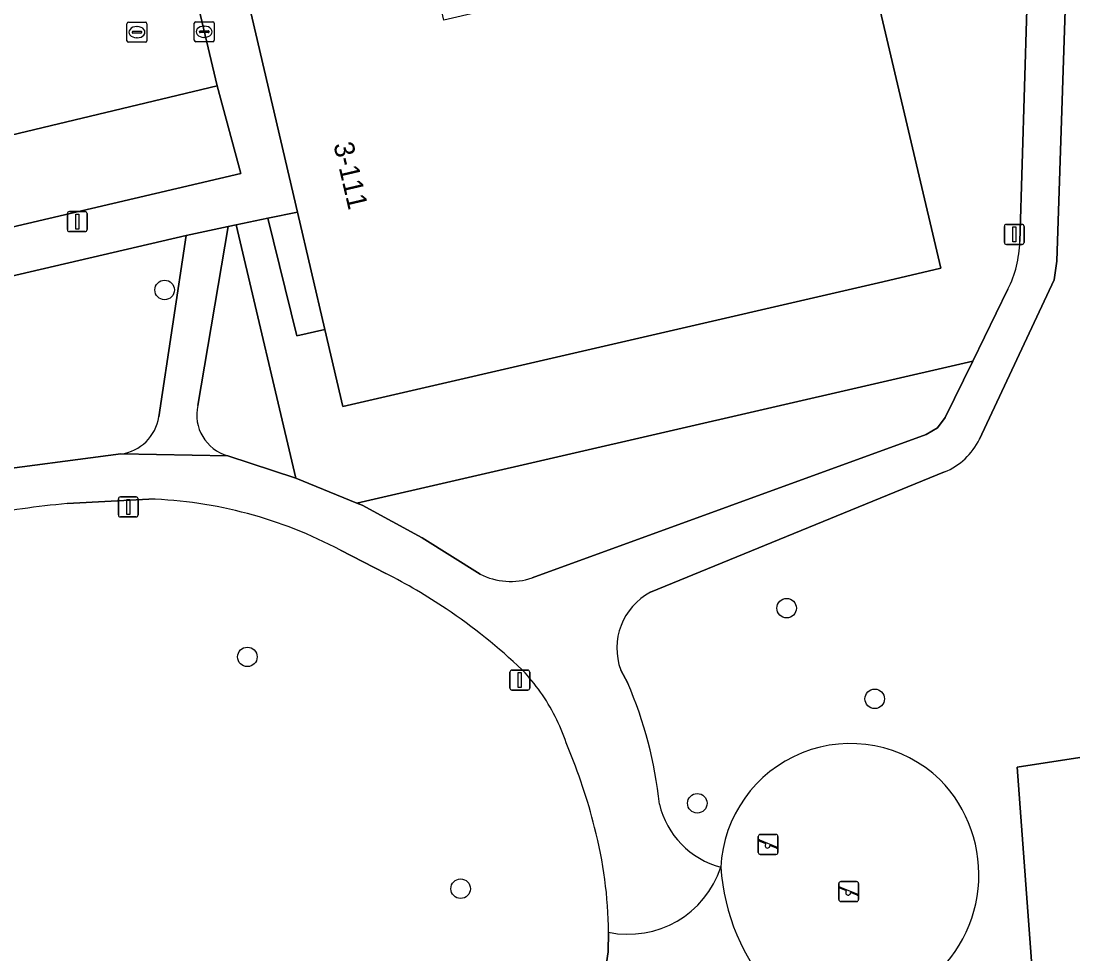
# Model space of a CAD drawing. Extents: x 162989 to 165008, y 383432 to 384338.
# Drawn here: x 164242.3 to 164294.9, y 383999.9 to 384046.6 of the extents above; entities that cross this region are included whole.
import ezdxf

# ---------------------------------------------------------------- set-up
doc = ezdxf.new("R2010")
doc.units = 0
for name, color, linetype in [('IMGEO_Boom', 7, 'Continuous'), ('IMGEO_Groenvoorziening', 7, 'Continuous'), ('IMGEO_Kolk', 7, 'Continuous'), ('IMGEO_Lichtmast', 7, 'Continuous'), ('IMGEO_Pand', 7, 'Continuous'), ('IMGEO_Pand_nummerreeks', 7, 'Continuous'), ('IMGEO_Parkeervlak_open', 7, 'Continuous'), ('IMGEO_Rijbaan_lokaal_open', 7, 'Continuous'), ('IMGEO_Rioolput', 7, 'Continuous'), ('IMGEO_Speelvoorziening', 7, 'Continuous'), ('IMGEO_Terreindeel_zand', 7, 'Continuous'), ('IMGEO_Voetpad_halfverhard', 7, 'Continuous'), ('IMGEO_Voetpad_open', 7, 'Continuous')]:
    doc.layers.add(name, color=color, linetype=linetype)

msp = doc.modelspace()

# ---------------------------------------------------------------- linework, layer by layer
at = {"layer": 'IMGEO_Boom'}
for centre in [(164249.448, 384033.16), (164280.603, 384017.221), (164253.594, 384014.78), (164285.014, 384012.681), (164276.127, 384007.448), (164264.273, 384003.167)]:
    msp.add_circle(centre, 0.489, dxfattribs=at)
at = {"layer": 'IMGEO_Groenvoorziening'}
for points in [[(164292.635, 384047.208), (164292.541, 384048.333), (164292.196, 384049.407), (164286.261, 384062.529), (164281.903, 384061.564), (164288.333, 384034.258), (164285.413, 384033.57), (164258.372, 384027.327), (164257.473, 384031.176), (164256.075, 384030.857), (164254.622, 384036.755), (164253.03, 384036.418), (164256.016, 384023.727), (164259.077, 384022.478), (164289.927, 384029.594), (164291.689, 384033.191)], [(164288.662, 383977.2), (164291.436, 383987.559), (164293.255, 383994.351), (164292.153, 384009.25), (164298.429, 384010.231), (164302.896, 384010.93), (164302.184, 384018.925), (164303.688, 384019.058), (164302.638, 384030.22), (164301.02, 384044.871), (164300.356, 384050.053), (164296.87, 384049.974)], [(164294.565, 384047.692), (164294.135, 384034.602), (164294.005, 384033.662), (164290.264, 384025.69)], [(164292.281, 384035.58), (164292.635, 384047.208)], [(164252.611, 384024.853), (164256.016, 384023.727), (164253.03, 384036.418), (164252.631, 384036.334), (164251.113, 384027.38)], [(164250.523, 384035.89), (164219.256, 384028.614)], [(164249.155, 384026.801), (164250.523, 384035.89)], [(164267.856, 384018.733), (164287.588, 384025.916), (164288.15, 384026.253), (164288.546, 384026.776), (164289.927, 384029.594), (164259.077, 384022.478), (164259.336, 384022.372), (164262.347, 384020.743), (164265.248, 384018.924)], [(164225.417, 384013.866), (164225.853, 384017.514), (164231.789, 384024.158), (164238.652, 384025.667), (164240.139, 384024.02), (164247.256, 384024.944)], [(164288.506, 384024.043), (164273.789, 384018.015)], [(164248.662, 384022.685), (164244.559, 384022.458)], [(164260.534, 384018.953), (164258.25, 384020.124)], [(164267.498, 384013.98), (164267.349, 384014.14)], [(164272.293, 384014.122), (164272.64, 384013.47)], [(164290.879, 383971.484), (164291.851, 383971.193), (164292.788, 383970.802), (164293.679, 383970.315), (164294.514, 383969.738), (164295.284, 383969.077), (164295.981, 383968.339), (164296.597, 383967.532), (164297.125, 383966.665), (164297.559, 383965.747), (164297.895, 383964.79), (164298.179, 383963.584), (164302.701, 383965.175), (164298.429, 384010.231), (164292.153, 384009.25), (164293.255, 383994.351), (164291.436, 383987.559)], [(164271.013, 383995.709), (164271.664, 384000), (164271.682, 384000.988)]]:
    msp.add_lwpolyline(points, dxfattribs=at)
for centre, radius, start, end in [((164286.473, 384035.751), 5.81, 333.8545, 358.3102), ((164253.187, 384026.902), 2.129, 167.0253, 254.2935), ((164246.972, 384027.133), 2.208, 277.3797, 351.339), ((164287.247, 384027.149), 3.351, 292.07, 334.1957), ((164248.547, 383978.561), 44.077, 95.1909, 101.0404), ((164247.985, 384000.923), 21.773, 61.8717, 88.2186), ((164247.779, 383993.698), 28.293, 56.1156, 63.2041), ((164266.783, 384021.988), 3.427, 243.3855, 288.2372), ((164275.259, 384015.216), 3.162, 117.7122, 200.2463), ((164246.823, 383992.448), 29.864, 46.5816, 55.9296), ((164260.237, 384007.364), 9.823, 34.1148, 42.3413), ((164253.699, 384005.254), 20.646, 5.9991, 23.4489), ((164260.132, 384007.271), 9.963, 17.7133, 34.2161), ((164244.197, 383999.509), 27.621, 14.0974, 23.0007), ((164283.794, 384003.946), 6.493, 46.2914, 177.3582), ((164283.431, 384003.87), 6.801, 303.4823, 44.5231), ((164278.385, 384008.368), 4.261, 192.9663, 255.3635), ((164250.156, 384000.804), 21.527, 0.4887, 14.6176)]:
    msp.add_arc(centre, radius, start, end, dxfattribs=at)
at = {"layer": 'IMGEO_Kolk'}
for p, q in [((164250.931, 384045.664), (164250.931, 384046.516)), ((164251.006, 384046.59), (164251.858, 384046.59)), ((164251.19, 384046.084), (164251.19, 384046.096)), ((164251.233, 384046.133), (164251.631, 384046.133)), ((164251.419, 384046.37), (164251.444, 384046.37)), ((164251.674, 384046.096), (164251.674, 384046.084)), ((164251.932, 384046.516), (164251.932, 384045.664)), ((164251.858, 384045.59), (164251.006, 384045.59)), ((164251.628, 384046.047), (164251.23, 384046.047)), ((164251.442, 384045.81), (164251.417, 384045.81))]:
    msp.add_line(p, q, dxfattribs=at)
for points in [[(164250.931, 384045.664), (164250.931, 384046.516)], [(164251.006, 384046.59), (164251.858, 384046.59)], [(164251.932, 384046.516), (164251.932, 384045.664)], [(164251.858, 384045.59), (164251.006, 384045.59)]]:
    msp.add_lwpolyline(points, dxfattribs=at)
for centre, radius, start, end in [((164251.008, 384046.514), 0.0765, 91.552, 178.448), ((164251.008, 384046.514), 0.0765, 91.552, 178.448), ((164251.23, 384046.093), 0.0403, 85.8775, 175.7526), ((164251.635, 384046.095), 0.0386, 1.7309, 96.639), ((164251.856, 384046.514), 0.0765, 1.552, 88.448), ((164251.856, 384046.514), 0.0765, 1.552, 88.448), ((164251.008, 384045.666), 0.0765, 181.552, 268.448), ((164251.008, 384045.666), 0.0765, 181.552, 268.448), ((164251.227, 384046.083), 0.0366, 178.938, 274.7102), ((164251.631, 384046.09), 0.043, 264.8664, 352.4533), ((164251.856, 384045.666), 0.0765, 271.552, 358.448), ((164251.856, 384045.666), 0.0765, 271.552, 358.448)]:
    msp.add_arc(centre, radius, start, end, dxfattribs=at)
for centre, major_axis, ratio, start_param, end_param in [((164251.418, 384046.09), (-0.387, 0.002), 0.722429, 4.712389, 7.853982), ((164251.443, 384046.09), (-0.39, 0.002), 0.717154, 1.570796, 4.712389)]:
    msp.add_ellipse(centre, major_axis=major_axis, ratio=ratio, start_param=start_param, end_param=end_param, dxfattribs=at)
at = {"layer": 'IMGEO_Lichtmast'}
for p, q in [((164244.576, 384036.182), (164244.576, 384036.982)), ((164244.576, 384036.982), (164244.576, 384036.182)), ((164244.676, 384037.082), (164245.466, 384037.082)), ((164245.466, 384037.082), (164244.676, 384037.082)), ((164245.566, 384036.982), (164245.566, 384036.182)), ((164245.566, 384036.182), (164245.566, 384036.982)), ((164245.466, 384036.082), (164244.676, 384036.082)), ((164244.676, 384036.082), (164245.466, 384036.082)), ((164291.508, 384035.543), (164291.508, 384036.343)), ((164291.508, 384036.343), (164291.508, 384035.543)), ((164291.608, 384036.443), (164292.398, 384036.443)), ((164292.398, 384036.443), (164291.608, 384036.443)), ((164292.498, 384036.343), (164292.498, 384035.543)), ((164292.498, 384035.543), (164292.498, 384036.343)), ((164292.398, 384035.443), (164291.608, 384035.443)), ((164291.608, 384035.443), (164292.398, 384035.443)), ((164247.13, 384021.889), (164247.13, 384022.689)), ((164247.13, 384022.689), (164247.13, 384021.889)), ((164247.23, 384022.789), (164248.02, 384022.789)), ((164248.02, 384022.789), (164247.23, 384022.789)), ((164248.12, 384022.689), (164248.12, 384021.889)), ((164248.12, 384021.889), (164248.12, 384022.689)), ((164248.02, 384021.789), (164247.23, 384021.789)), ((164247.23, 384021.789), (164248.02, 384021.789)), ((164266.743, 384013.218), (164266.743, 384014.018)), ((164266.743, 384014.018), (164266.743, 384013.218)), ((164266.843, 384014.118), (164267.633, 384014.118)), ((164267.633, 384014.118), (164266.843, 384014.118)), ((164267.733, 384014.018), (164267.733, 384013.218)), ((164267.733, 384013.218), (164267.733, 384014.018)), ((164267.633, 384013.118), (164266.843, 384013.118)), ((164266.843, 384013.118), (164267.633, 384013.118))]:
    msp.add_line(p, q, dxfattribs=at)
for points in [[(164244.996, 384036.957), (164245.146, 384036.957), (164245.146, 384036.207), (164244.996, 384036.207), (164244.996, 384036.957)], [(164291.928, 384036.318), (164292.078, 384036.318), (164292.078, 384035.568), (164291.928, 384035.568), (164291.928, 384036.318)], [(164247.55, 384022.664), (164247.7, 384022.664), (164247.7, 384021.914), (164247.55, 384021.914), (164247.55, 384022.664)], [(164267.163, 384013.993), (164267.313, 384013.993), (164267.313, 384013.243), (164267.163, 384013.243), (164267.163, 384013.993)]]:
    msp.add_lwpolyline(points, dxfattribs=at)
for centre, start, end in [((164244.676, 384036.982), 90, 180), ((164244.676, 384036.982), 90, 180), ((164245.466, 384036.982), 0, 90), ((164245.466, 384036.982), 360, 90), ((164244.676, 384036.182), 180, 270), ((164244.676, 384036.182), 180, 270), ((164245.466, 384036.182), 270, 0), ((164245.466, 384036.182), 270, 0), ((164291.608, 384036.343), 90, 180), ((164291.608, 384036.343), 90, 180), ((164292.398, 384036.343), 0, 90), ((164292.398, 384036.343), 360, 90), ((164291.608, 384035.543), 180, 270), ((164291.608, 384035.543), 180, 270), ((164292.398, 384035.543), 270, 0), ((164292.398, 384035.543), 270, 0), ((164247.23, 384022.689), 90, 180), ((164247.23, 384022.689), 90, 180), ((164248.02, 384022.689), 0, 90), ((164248.02, 384022.689), 360, 90), ((164247.23, 384021.889), 180, 270), ((164247.23, 384021.889), 180, 270), ((164248.02, 384021.889), 270, 0), ((164248.02, 384021.889), 270, 0), ((164266.843, 384014.018), 90, 180), ((164266.843, 384014.018), 90, 180), ((164267.633, 384014.018), 0, 90), ((164267.633, 384014.018), 360, 90), ((164266.843, 384013.218), 180, 270), ((164266.843, 384013.218), 180, 270), ((164267.633, 384013.218), 270, 0), ((164267.633, 384013.218), 270, 0)]:
    msp.add_arc(centre, 0.1, start, end, dxfattribs=at)
at = {"layer": 'IMGEO_Pand'}
msp.add_lwpolyline([(164281.903, 384061.564), (164272.695, 384059.396), (164274.092, 384054.262), (164274.51, 384052.47), (164274.837, 384051.068), (164270.485, 384050.053), (164270.869, 384048.402), (164263.436, 384046.666), (164262.745, 384049.627), (164262.679, 384049.912), (164254.084, 384047.905), (164253.594, 384047.791), (164256.099, 384037.062), (164257.473, 384031.176), (164258.372, 384027.327), (164285.413, 384033.57), (164288.333, 384034.258)], close=True, dxfattribs=at)
at = {"layer": 'IMGEO_Parkeervlak_open'}
msp.add_lwpolyline([(164216.414, 384032.688), (164216.912, 384030.477), (164253.269, 384038.999), (164252.072, 384043.378), (164228.984, 384037.862), (164226.367, 384037.236), (164213.994, 384034.28)], dxfattribs=at)
at = {"layer": 'IMGEO_Rijbaan_lokaal_open'}
msp.add_lwpolyline([(164236.086, 384046.718), (164227.391, 384044.691), (164228.984, 384037.862), (164252.072, 384043.378), (164249.058, 384056.151), (164247.449, 384062.968), (164245.302, 384072.068), (164243.675, 384078.963), (164235.037, 384115.701)], dxfattribs=at)
at = {"layer": 'IMGEO_Rioolput'}
for p, q in [((164247.561, 384045.644), (164247.561, 384046.496)), ((164247.636, 384046.57), (164248.488, 384046.57)), ((164247.863, 384046.113), (164248.261, 384046.113)), ((164248.049, 384046.35), (164248.074, 384046.35)), ((164248.562, 384046.496), (164248.562, 384045.644)), ((164248.488, 384045.57), (164247.636, 384045.57)), ((164247.82, 384046.064), (164247.82, 384046.076)), ((164248.258, 384046.027), (164247.86, 384046.027)), ((164248.072, 384045.79), (164248.047, 384045.79)), ((164248.304, 384046.076), (164248.304, 384046.064))]:
    msp.add_line(p, q, dxfattribs=at)
for points in [[(164247.561, 384045.644), (164247.561, 384046.496)], [(164247.636, 384046.57), (164248.488, 384046.57)], [(164248.562, 384046.496), (164248.562, 384045.644)], [(164248.488, 384045.57), (164247.636, 384045.57)]]:
    msp.add_lwpolyline(points, dxfattribs=at)
for centre, radius, start, end in [((164247.638, 384046.494), 0.0765, 91.552, 178.448), ((164247.638, 384046.494), 0.0765, 91.552, 178.448), ((164247.86, 384046.073), 0.0403, 85.8775, 175.7526), ((164248.265, 384046.075), 0.0386, 1.7309, 96.639), ((164248.486, 384046.494), 0.0765, 1.552, 88.448), ((164248.486, 384046.494), 0.0765, 1.552, 88.448), ((164247.638, 384045.646), 0.0765, 181.552, 268.448), ((164247.638, 384045.646), 0.0765, 181.552, 268.448), ((164247.857, 384046.063), 0.0366, 178.938, 274.7102), ((164248.261, 384046.07), 0.043, 264.8664, 352.4533), ((164248.486, 384045.646), 0.0765, 271.552, 358.448), ((164248.486, 384045.646), 0.0765, 271.552, 358.448)]:
    msp.add_arc(centre, radius, start, end, dxfattribs=at)
for centre, major_axis, ratio, start_param, end_param in [((164248.048, 384046.07), (-0.387, 0.002), 0.722429, 4.712389, 7.853982), ((164248.073, 384046.07), (-0.39, 0.002), 0.717154, 1.570796, 4.712389)]:
    msp.add_ellipse(centre, major_axis=major_axis, ratio=ratio, start_param=start_param, end_param=end_param, dxfattribs=at)
at = {"layer": 'IMGEO_Speelvoorziening'}
for p, q in [((164279.178, 384004.985), (164279.178, 384005.785)), ((164279.178, 384005.785), (164279.178, 384004.985)), ((164279.561, 384005.413), (164279.222, 384005.55)), ((164279.247, 384005.61), (164280.123, 384005.257)), ((164279.278, 384005.885), (164280.068, 384005.885)), ((164280.068, 384005.885), (164279.278, 384005.885)), ((164280.168, 384005.785), (164280.168, 384004.985)), ((164280.168, 384004.985), (164280.168, 384005.785)), ((164280.099, 384005.197), (164279.759, 384005.334)), ((164280.068, 384004.885), (164279.278, 384004.885)), ((164279.278, 384004.885), (164280.068, 384004.885)), ((164283.215, 384002.629), (164283.215, 384003.429)), ((164283.215, 384003.429), (164283.215, 384002.629)), ((164283.315, 384003.529), (164284.105, 384003.529)), ((164284.105, 384003.529), (164283.315, 384003.529)), ((164284.205, 384003.429), (164284.205, 384002.629)), ((164284.205, 384002.629), (164284.205, 384003.429)), ((164283.598, 384003.057), (164283.259, 384003.194)), ((164283.284, 384003.254), (164284.16, 384002.901)), ((164284.136, 384002.841), (164283.796, 384002.978)), ((164284.105, 384002.529), (164283.315, 384002.529)), ((164283.315, 384002.529), (164284.105, 384002.529))]:
    msp.add_line(p, q, dxfattribs=at)
for centre, radius, start, end in [((164279.278, 384005.785), 0.1, 90, 180), ((164279.278, 384005.785), 0.1, 90, 180), ((164279.235, 384005.58), 0.0327, 68.078, 248.078), ((164280.068, 384005.785), 0.1, 0, 90), ((164280.068, 384005.785), 0.1, 360, 90), ((164279.64, 384005.323), 0.12, 130.9928, 5.1632), ((164280.111, 384005.227), 0.0327, 248.078, 68.078), ((164279.278, 384004.985), 0.1, 180, 270), ((164279.278, 384004.985), 0.1, 180, 270), ((164280.068, 384004.985), 0.1, 270, 0), ((164280.068, 384004.985), 0.1, 270, 0), ((164283.315, 384003.429), 0.1, 90, 180), ((164283.315, 384003.429), 0.1, 90, 180), ((164284.105, 384003.429), 0.1, 0, 90), ((164284.105, 384003.429), 0.1, 360, 90), ((164283.272, 384003.224), 0.0327, 68.078, 248.078), ((164283.677, 384002.967), 0.12, 130.9928, 5.1632), ((164284.148, 384002.871), 0.0327, 248.078, 68.078), ((164283.315, 384002.629), 0.1, 180, 270), ((164283.315, 384002.629), 0.1, 180, 270), ((164284.105, 384002.629), 0.1, 270, 0), ((164284.105, 384002.629), 0.1, 270, 0)]:
    msp.add_arc(centre, radius, start, end, dxfattribs=at)
at = {"layer": 'IMGEO_Terreindeel_zand'}
for centre, radius, start, end in [((164283.794, 384003.946), 6.493, 46.2914, 177.3582), ((164283.431, 384003.87), 6.801, 303.4823, 44.5231), ((164287.842, 384004.937), 10.556, 183.7578, 221.7258)]:
    msp.add_arc(centre, radius, start, end, dxfattribs=at)
at = {"layer": 'IMGEO_Voetpad_halfverhard'}
for points in [[(164291.955, 384054.83), (164288.224, 384062.997), (164286.261, 384062.529), (164292.196, 384049.407), (164292.541, 384048.333), (164292.635, 384047.208), (164292.281, 384035.58)], [(164290.264, 384025.69), (164294.005, 384033.662), (164294.135, 384034.602), (164294.565, 384047.692), (164293.767, 384052.02), (164292.649, 384053.999)], [(164252.631, 384036.334), (164250.523, 384035.89), (164249.155, 384026.801)], [(164251.113, 384027.38), (164252.631, 384036.334)], [(164291.689, 384033.191), (164289.927, 384029.594), (164288.546, 384026.776), (164288.15, 384026.253), (164287.588, 384025.916), (164267.856, 384018.733)], [(164265.248, 384018.924), (164262.347, 384020.743), (164259.336, 384022.372), (164259.077, 384022.478), (164256.016, 384023.727), (164252.611, 384024.853), (164247.256, 384024.944), (164240.139, 384024.02), (164232.148, 384022.19), (164225.417, 384013.866)], [(164247.256, 384024.944), (164252.611, 384024.853)], [(164273.789, 384018.015), (164288.506, 384024.043)], [(164244.559, 384022.458), (164248.662, 384022.685)], [(164258.25, 384020.124), (164260.534, 384018.953)], [(164267.349, 384014.14), (164267.498, 384013.98)], [(164272.64, 384013.47), (164272.293, 384014.122)]]:
    msp.add_lwpolyline(points, dxfattribs=at)
for centre, radius, start, end in [((164286.473, 384035.751), 5.81, 333.8545, 358.3102), ((164253.187, 384026.902), 2.129, 167.0253, 254.2935), ((164246.972, 384027.133), 2.208, 277.3797, 351.339), ((164287.247, 384027.149), 3.351, 292.07, 334.1957), ((164248.547, 383978.561), 44.077, 95.1909, 101.0404), ((164247.985, 384000.923), 21.773, 61.8717, 88.2186), ((164247.779, 383993.698), 28.293, 56.1156, 63.2041), ((164266.783, 384021.988), 3.427, 243.3855, 288.2372), ((164275.259, 384015.216), 3.162, 117.7122, 200.2463), ((164246.823, 383992.448), 29.864, 46.5816, 55.9296), ((164260.237, 384007.364), 9.823, 34.1148, 42.3413), ((164253.699, 384005.254), 20.646, 5.9991, 23.4489), ((164260.132, 384007.271), 9.963, 17.7133, 34.2161), ((164244.197, 383999.509), 27.621, 14.0974, 23.0007), ((164278.385, 384008.368), 4.261, 192.9663, 255.3635), ((164250.156, 384000.804), 21.527, 0.4887, 14.6176), ((164272.66, 384005.786), 4.897, 258.4783, 341.6564)]:
    msp.add_arc(centre, radius, start, end, dxfattribs=at)
at = {"layer": 'IMGEO_Voetpad_open'}
for points in [[(164251.984, 384056.901), (164251.498, 384056.784), (164249.537, 384056.266), (164249.058, 384056.151), (164252.072, 384043.378), (164253.269, 384038.999), (164216.912, 384030.477), (164216.414, 384032.688), (164214.083, 384031.794), (164215.173, 384027.177), (164218.086, 384027.777)], [(164219.256, 384028.614), (164250.523, 384035.89), (164252.631, 384036.334), (164253.03, 384036.418), (164254.622, 384036.755), (164256.099, 384037.062), (164253.594, 384047.791), (164254.084, 384047.905), (164251.984, 384056.901)], [(164271.682, 384000.988), (164271.664, 384000), (164271.013, 383995.709)]]:
    msp.add_lwpolyline(points, dxfattribs=at)
msp.add_lwpolyline([(164256.099, 384037.062), (164254.622, 384036.755), (164256.075, 384030.857), (164257.473, 384031.176)], close=True, dxfattribs=at)
for centre, radius, start, end in [((164272.66, 384005.786), 4.897, 258.4783, 341.6564), ((164287.842, 384004.937), 10.556, 183.7578, 221.7258)]:
    msp.add_arc(centre, radius, start, end, dxfattribs=at)

# ---------------------------------------------------------------- texts
at = {"layer": 'IMGEO_Pand_nummerreeks'}
msp.add_text('3-111', height=1, rotation=283.1434, dxfattribs=at).set_placement((164257.896, 384040.45))

doc.saveas('drawing.dxf')
